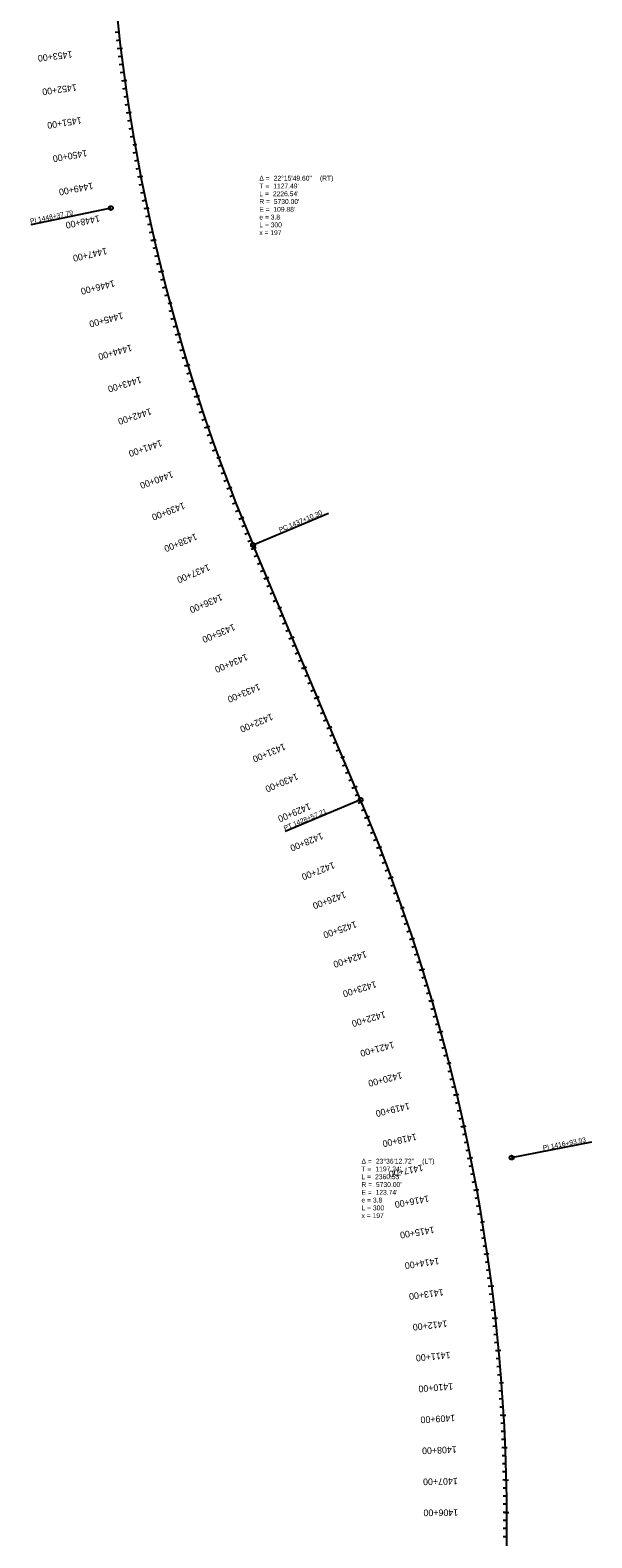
# Model space of a CAD drawing. Extents: x 20505176 to 20507119, y 7960287 to 7982631.
# Drawn here: x 20505239 to 20506971, y 7973323 to 7977971 of the extents above; entities that cross this region are included whole.
import ezdxf

# ---------------------------------------------------------------- set-up
doc = ezdxf.new("R2010")
doc.units = 0
for name, color, linetype in [('Alignment', 7, 'Continuous'), ('TextAlignment', 7, 'Continuous'), ('TextAlignmentLrg', 7, 'Continuous'), ('TextAlignmentSml', 7, 'Continuous')]:
    doc.layers.add(name, color=color, linetype=linetype)

msp = doc.modelspace()

# ---------------------------------------------------------------- linework, layer by layer
at = {"layer": 'Alignment'}
msp.add_line((20506257.8, 7975598.2), (20505926.1, 7976384.1), dxfattribs=at)
for centre, start, end in [((20511205.4, 7978611.7), 180.61343, 202.8772), ((20500978.6, 7973370.4), 359.27591, 22.87944)]:
    msp.add_arc(centre, 5730, start, end, dxfattribs=at)
at = {"layer": 'TextAlignment'}
for p, q in [((20505487.8, 7977422.9), (20505241.1, 7977371.6)), ((20505241.1, 7977371.6), (20505241.1, 7977371.6)), ((20505926.1, 7976384.1), (20506158.3, 7976482.1)), ((20506158.3, 7976482.1), (20506158.3, 7976482.1)), ((20506257.8, 7975598.2), (20506025.6, 7975500.2)), ((20506025.6, 7975500.2), (20506025.6, 7975500.2)), ((20506723.2, 7974495.1), (20506970.5, 7974543.5)), ((20506970.5, 7974543.5), (20506970.5, 7974543.5))]:
    msp.add_line(p, q, dxfattribs=at)
for centre in [(20505487.8, 7977422.9), (20505926.1, 7976384.1), (20506257.8, 7975598.2), (20506723.2, 7974495.1)]:
    msp.add_circle(centre, 6.24, dxfattribs=at)
at = {"layer": 'TextAlignmentLrg'}
for p, q in [((20505517.9, 7977915.3), (20505507, 7977913.9)), ((20505530.9, 7977816.1), (20505520.1, 7977814.6)), ((20505545.7, 7977717.2), (20505534.9, 7977715.5)), ((20505556.1, 7977617.5), (20505568.2, 7977619.6)), ((20505580.3, 7977520.2), (20505569.6, 7977518.2)), ((20505600.2, 7977422.2), (20505589.5, 7977420)), ((20505621.8, 7977324.6), (20505611.2, 7977322.2)), ((20505645.1, 7977227.4), (20505634.6, 7977224.7)), ((20505664.2, 7977129), (20505676.1, 7977132.1)), ((20505696.8, 7977034.2), (20505686.3, 7977031.2)), ((20505725.2, 7976938.3), (20505714.8, 7976935.1)), ((20505755.3, 7976842.9), (20505744.9, 7976839.5)), ((20505786.9, 7976748.1), (20505776.6, 7976744.5)), ((20505814.5, 7976651.7), (20505826, 7976655.9)), ((20505855.3, 7976560.1), (20505845.1, 7976556.2)), ((20505891.9, 7976467.1), (20505881.8, 7976463)), ((20505930.1, 7976374.7), (20505920.1, 7976370.4)), ((20505969, 7976282.5), (20505958.9, 7976278.3)), ((20506002.2, 7976188), (20506013.5, 7976192.8)), ((20506046.8, 7976098.2), (20506036.7, 7976094)), ((20506085.6, 7976006.1), (20506075.6, 7976001.9)), ((20506124.5, 7975914), (20506114.4, 7975909.7)), ((20506163.4, 7975821.8), (20506153.3, 7975817.6)), ((20506196.6, 7975727.3), (20506207.9, 7975732.1)), ((20506241.1, 7975637.6), (20506231.1, 7975633.3)), ((20506279.7, 7975545.3), (20506269.6, 7975541.2)), ((20506316.9, 7975452.5), (20506306.7, 7975448.5)), ((20506352.4, 7975359), (20506342.2, 7975355.2)), ((20506380.5, 7975262.9), (20506392.1, 7975267)), ((20506418.5, 7975170.3), (20506408.2, 7975166.8)), ((20506449.1, 7975075.1), (20506438.7, 7975071.8)), ((20506478, 7974979.3), (20506467.5, 7974976.3)), ((20506505.3, 7974883.1), (20506494.7, 7974880.2)), ((20506524.9, 7974784.9), (20506536.8, 7974788)), ((20506554.7, 7974689.3), (20506544.1, 7974686.8)), ((20506576.9, 7974591.8), (20506566.2, 7974589.5)), ((20506597.3, 7974493.9), (20506586.6, 7974491.8)), ((20506616.1, 7974395.7), (20506605.3, 7974393.8)), ((20506627.1, 7974296.2), (20506639.2, 7974298.2)), ((20506648.4, 7974198.4), (20506637.6, 7974196.8)), ((20506662, 7974099.3), (20506651.2, 7974097.9)), ((20506673.9, 7974000), (20506663, 7973998.8)), ((20506684, 7973900.5), (20506673.1, 7973899.5)), ((20506686.3, 7973800.4), (20506698.5, 7973801.3)), ((20506699, 7973701.1), (20506688.1, 7973700.5)), ((20506703.9, 7973601.2), (20506693, 7973600.8)), ((20506707.1, 7973501.3), (20506696.2, 7973501)), ((20506708.5, 7973401.3), (20506697.6, 7973401.2))]:
    msp.add_line(p, q, dxfattribs=at)
at = {"layer": 'TextAlignmentSml'}
for p, q in [((20505512, 7977964.9), (20505501.2, 7977963.7)), ((20505514.9, 7977940.1), (20505504.1, 7977938.8)), ((20505511.8, 7977914.5), (20505524, 7977916)), ((20505521, 7977890.4), (20505510.1, 7977889.1)), ((20505524.2, 7977865.7), (20505513.4, 7977864.2)), ((20505527.5, 7977840.9), (20505516.7, 7977839.4)), ((20505524.8, 7977815.3), (20505537, 7977817)), ((20505534.4, 7977791.4), (20505523.6, 7977789.8)), ((20505538.1, 7977766.6), (20505527.3, 7977765)), ((20505541.8, 7977741.9), (20505531, 7977740.2)), ((20505539.6, 7977716.2), (20505551.7, 7977718.2)), ((20505549.6, 7977692.5), (20505538.8, 7977690.8)), ((20505553.7, 7977667.9), (20505542.9, 7977666.1)), ((20505557.8, 7977643.2), (20505547.1, 7977641.4)), ((20505556.1, 7977617.5), (20505568.2, 7977619.6)), ((20505566.5, 7977594), (20505555.8, 7977592)), ((20505571, 7977569.4), (20505560.3, 7977567.4)), ((20505575.6, 7977544.8), (20505564.9, 7977542.8)), ((20505574.3, 7977519.1), (20505586.3, 7977521.4)), ((20505585.1, 7977495.7), (20505574.4, 7977493.6)), ((20505590.1, 7977471.2), (20505579.4, 7977469)), ((20505595.1, 7977446.7), (20505584.4, 7977444.5)), ((20505594.2, 7977421), (20505606.2, 7977423.5)), ((20505605.5, 7977397.8), (20505594.8, 7977395.5)), ((20505610.8, 7977373.4), (20505600.2, 7977371)), ((20505616.3, 7977349), (20505605.6, 7977346.6)), ((20505615.9, 7977323.2), (20505627.8, 7977326)), ((20505627.5, 7977300.3), (20505616.9, 7977297.8)), ((20505633.3, 7977275.9), (20505622.7, 7977273.4)), ((20505639.2, 7977251.6), (20505628.6, 7977249)), ((20505639.2, 7977225.9), (20505651.1, 7977228.8)), ((20505651.2, 7977203.1), (20505640.7, 7977200.4)), ((20505657.4, 7977178.9), (20505646.9, 7977176.2)), ((20505663.7, 7977154.7), (20505653.2, 7977151.9)), ((20505664.2, 7977129), (20505676.1, 7977132.1)), ((20505676.7, 7977106.4), (20505666.1, 7977103.5)), ((20505683.3, 7977082.3), (20505672.8, 7977079.4)), ((20505690, 7977058.2), (20505679.5, 7977055.3)), ((20505691, 7977032.5), (20505702.7, 7977035.9)), ((20505703.8, 7977010.2), (20505693.3, 7977007.1)), ((20505710.8, 7976986.2), (20505700.3, 7976983.1)), ((20505718, 7976962.2), (20505707.5, 7976959.1)), ((20505719.4, 7976936.5), (20505731.1, 7976940.1)), ((20505732.6, 7976914.4), (20505722.1, 7976911.2)), ((20505740, 7976890.5), (20505729.6, 7976887.2)), ((20505747.6, 7976866.7), (20505737.2, 7976863.4)), ((20505749.4, 7976841), (20505761.1, 7976844.8)), ((20505763, 7976819.1), (20505752.6, 7976815.7)), ((20505770.9, 7976795.4), (20505760.5, 7976791.9)), ((20505778.9, 7976771.7), (20505768.5, 7976768.2)), ((20505781.2, 7976746.1), (20505792.7, 7976750.1)), ((20505795.1, 7976724.4), (20505784.8, 7976720.8)), ((20505803.4, 7976700.8), (20505793.1, 7976697.2)), ((20505811.8, 7976677.3), (20505801.5, 7976673.6)), ((20505814.5, 7976651.7), (20505826, 7976655.9)), ((20505828.9, 7976630.3), (20505818.6, 7976626.5)), ((20505837.6, 7976606.9), (20505827.4, 7976603)), ((20505846.4, 7976583.5), (20505836.2, 7976579.6)), ((20505849.6, 7976557.9), (20505861, 7976562.3)), ((20505864.3, 7976536.8), (20505854.1, 7976532.8)), ((20505873.4, 7976513.5), (20505863.2, 7976509.5)), ((20505882.6, 7976490.3), (20505872.5, 7976486.2)), ((20505886.2, 7976464.8), (20505897.6, 7976469.3)), ((20505901.3, 7976443.9), (20505891.2, 7976439.8)), ((20505910.8, 7976420.8), (20505900.7, 7976416.6)), ((20505920.4, 7976397.7), (20505910.4, 7976393.5)), ((20505924.5, 7976372.3), (20505935.8, 7976377)), ((20505939.8, 7976351.6), (20505929.8, 7976347.4)), ((20505949.6, 7976328.6), (20505939.5, 7976324.3)), ((20505959.3, 7976305.5), (20505949.2, 7976301.3)), ((20505963.4, 7976280.1), (20505974.6, 7976284.9)), ((20505978.7, 7976259.5), (20505968.7, 7976255.2)), ((20505988.4, 7976236.4), (20505978.4, 7976232.2)), ((20505998.2, 7976213.4), (20505988.1, 7976209.2)), ((20506002.2, 7976188), (20506013.5, 7976192.8)), ((20506017.6, 7976167.3), (20506007.5, 7976163.1)), ((20506027.3, 7976144.3), (20506017.3, 7976140.1)), ((20506037, 7976121.3), (20506027, 7976117)), ((20506041.1, 7976095.9), (20506052.4, 7976100.6)), ((20506056.5, 7976075.2), (20506046.4, 7976071)), ((20506066.2, 7976052.2), (20506056.1, 7976047.9)), ((20506075.9, 7976029.1), (20506065.8, 7976024.9)), ((20506080, 7976003.7), (20506091.3, 7976008.5)), ((20506095.3, 7975983.1), (20506085.3, 7975978.8)), ((20506105.1, 7975960), (20506095, 7975955.8)), ((20506114.8, 7975937), (20506104.7, 7975932.8)), ((20506118.9, 7975911.6), (20506130.1, 7975916.4)), ((20506134.2, 7975890.9), (20506124.2, 7975886.7)), ((20506143.9, 7975867.9), (20506133.9, 7975863.7)), ((20506153.7, 7975844.9), (20506143.6, 7975840.6)), ((20506157.7, 7975819.5), (20506169, 7975824.2)), ((20506173.1, 7975798.8), (20506163, 7975794.6)), ((20506182.8, 7975775.8), (20506172.8, 7975771.5)), ((20506192.5, 7975752.7), (20506182.5, 7975748.5)), ((20506196.6, 7975727.3), (20506207.9, 7975732.1)), ((20506212, 7975706.7), (20506201.9, 7975702.4)), ((20506221.7, 7975683.6), (20506211.6, 7975679.4)), ((20506231.4, 7975660.6), (20506221.3, 7975656.4)), ((20506235.5, 7975635.2), (20506246.8, 7975640)), ((20506250.8, 7975614.5), (20506240.8, 7975610.3)), ((20506260.6, 7975591.5), (20506250.5, 7975587.3)), ((20506270.2, 7975568.4), (20506260.1, 7975564.2)), ((20506274.1, 7975543), (20506285.4, 7975547.7)), ((20506289.2, 7975522.2), (20506279.1, 7975518.1)), ((20506298.5, 7975499), (20506288.4, 7975494.9)), ((20506307.8, 7975475.8), (20506297.6, 7975471.7)), ((20506311.2, 7975450.3), (20506322.6, 7975454.7)), ((20506325.9, 7975429.2), (20506315.7, 7975425.3)), ((20506334.9, 7975405.8), (20506324.6, 7975401.9)), ((20506343.7, 7975382.4), (20506333.5, 7975378.6)), ((20506346.7, 7975356.9), (20506358.1, 7975361.1)), ((20506361, 7975335.5), (20506350.8, 7975331.8)), ((20506369.6, 7975312), (20506359.3, 7975308.3)), ((20506378, 7975288.5), (20506367.7, 7975284.8)), ((20506380.5, 7975262.9), (20506392.1, 7975267)), ((20506394.5, 7975241.3), (20506384.2, 7975237.8)), ((20506402.6, 7975217.7), (20506392.3, 7975214.1)), ((20506410.6, 7975194), (20506400.3, 7975190.5)), ((20506412.7, 7975168.3), (20506424.3, 7975172.2)), ((20506426.3, 7975146.5), (20506416, 7975143.1)), ((20506434, 7975122.7), (20506423.6, 7975119.4)), ((20506441.6, 7975098.9), (20506431.2, 7975095.6)), ((20506443.3, 7975073.2), (20506455, 7975076.9)), ((20506456.5, 7975051.2), (20506446.1, 7975048)), ((20506463.8, 7975027.3), (20506453.3, 7975024.1)), ((20506471, 7975003.3), (20506460.5, 7975000.2)), ((20506472.2, 7974977.6), (20506483.9, 7974981.1)), ((20506485, 7974955.3), (20506474.5, 7974952.3)), ((20506491.9, 7974931.3), (20506481.4, 7974928.3)), ((20506498.6, 7974907.2), (20506488.1, 7974904.3)), ((20506499.4, 7974881.5), (20506511.2, 7974884.7)), ((20506511.8, 7974859), (20506501.3, 7974856.2)), ((20506518.3, 7974834.8), (20506507.7, 7974832)), ((20506524.6, 7974810.7), (20506514, 7974807.9)), ((20506524.9, 7974784.9), (20506536.8, 7974788)), ((20506537, 7974762.2), (20506526.4, 7974759.5)), ((20506543, 7974737.9), (20506532.4, 7974735.3)), ((20506548.9, 7974713.6), (20506538.3, 7974711.1)), ((20506548.7, 7974687.9), (20506560.7, 7974690.7)), ((20506560.4, 7974665), (20506549.8, 7974662.5)), ((20506566, 7974640.6), (20506555.3, 7974638.2)), ((20506571.5, 7974616.2), (20506560.8, 7974613.9)), ((20506570.9, 7974590.5), (20506582.8, 7974593.1)), ((20506582.1, 7974567.4), (20506571.5, 7974565.1)), ((20506587.3, 7974542.9), (20506576.6, 7974540.7)), ((20506592.4, 7974518.4), (20506581.7, 7974516.3)), ((20506591.3, 7974492.7), (20506603.3, 7974495.1)), ((20506602.2, 7974469.4), (20506591.5, 7974467.3)), ((20506606.9, 7974444.9), (20506596.2, 7974442.8)), ((20506611.6, 7974420.3), (20506600.8, 7974418.3)), ((20506620.5, 7974371.1), (20506609.7, 7974369.2)), ((20506610.1, 7974394.6), (20506622.1, 7974396.8)), ((20506624.8, 7974346.5), (20506614, 7974344.6)), ((20506629, 7974321.8), (20506618.2, 7974320)), ((20506637.1, 7974272.5), (20506626.3, 7974270.8)), ((20506627.1, 7974296.2), (20506639.2, 7974298.2)), ((20506641, 7974247.8), (20506630.2, 7974246.1)), ((20506644.8, 7974223.1), (20506634, 7974221.5)), ((20506642.4, 7974197.5), (20506654.5, 7974199.2)), ((20506652, 7974173.6), (20506641.2, 7974172.1)), ((20506655.4, 7974148.9), (20506644.6, 7974147.4)), ((20506658.8, 7974124.1), (20506648, 7974122.6)), ((20506655.9, 7974098.5), (20506668.1, 7974100.1)), ((20506665.1, 7974074.5), (20506654.3, 7974073.1)), ((20506668.2, 7974049.7), (20506657.3, 7974048.4)), ((20506671.1, 7974024.8), (20506660.2, 7974023.6)), ((20506667.8, 7973999.3), (20506679.9, 7974000.7)), ((20506676.6, 7973975.1), (20506665.7, 7973974)), ((20506679.1, 7973950.3), (20506668.3, 7973949.2)), ((20506681.6, 7973925.4), (20506670.8, 7973924.3)), ((20506677.9, 7973899.9), (20506690.1, 7973901.1)), ((20506686.2, 7973875.6), (20506675.4, 7973874.6)), ((20506688.4, 7973850.7), (20506677.5, 7973849.8)), ((20506690.4, 7973825.8), (20506679.6, 7973824.9)), ((20506694.2, 7973775.9), (20506683.3, 7973775.2)), ((20506686.3, 7973800.4), (20506698.5, 7973801.3)), ((20506695.9, 7973751), (20506685, 7973750.3)), ((20506697.5, 7973726), (20506686.6, 7973725.4)), ((20506700.4, 7973676.1), (20506689.5, 7973675.5)), ((20506692.9, 7973700.7), (20506705.1, 7973701.4)), ((20506701.7, 7973651.2), (20506690.8, 7973650.6)), ((20506702.9, 7973626.2), (20506691.9, 7973625.7)), ((20506704.9, 7973576.2), (20506694, 7973575.8)), ((20506697.8, 7973601), (20506710, 7973601.4)), ((20506705.7, 7973551.2), (20506694.8, 7973550.9)), ((20506706.4, 7973526.2), (20506695.5, 7973525.9)), ((20506701, 7973501.1), (20506713.2, 7973501.4)), ((20506707.6, 7973476.3), (20506696.7, 7973476.1)), ((20506708, 7973451.3), (20506697.1, 7973451.1)), ((20506708.3, 7973426.3), (20506697.4, 7973426.2)), ((20506702.4, 7973401.2), (20506714.6, 7973401.3)), ((20506708.6, 7973376.3), (20506697.6, 7973376.3)), ((20506708.5, 7973351.3), (20506697.6, 7973351.3)), ((20506708.4, 7973326.3), (20506697.5, 7973326.3))]:
    msp.add_line(p, q, dxfattribs=at)

# ---------------------------------------------------------------- texts
at = {"layer": 'TextAlignment'}
for s, p in [(' (RT)', (20506126.5, 7977507.5)), ('T = ', (20505945.4, 7977483.5)), ('Δ = ', (20505945.4, 7977507.5)), ("1127.49'", (20505988.3, 7977483.5)), ('22°15\'49.60"', (20505989.8, 7977507.5)), ('L = ', (20505945.4, 7977459.5)), ('R = ', (20505945.4, 7977435.5)), ("2226.54'", (20505987.2, 7977459.5)), ("5730.00'", (20505990, 7977435.5)), ('e = 3.8', (20505945.4, 7977387.5)), ('E = ', (20505945.4, 7977411.5)), ("109.88'", (20505988.7, 7977411.5)), ('x = 197', (20505945.4, 7977339.5)), ('L = 300', (20505945.4, 7977363.5)), ('T = ', (20506260.5, 7974452.7)), ('Δ = ', (20506260.5, 7974476.7)), ("1197.24'", (20506303.4, 7974452.7)), ('23°36\'12.72"', (20506304.9, 7974476.7)), (' (LT)', (20506441.6, 7974476.7)), ('L = ', (20506260.5, 7974428.7)), ('R = ', (20506260.5, 7974404.7)), ("2360.53'", (20506302.3, 7974428.7)), ("5730.00'", (20506305.1, 7974404.7)), ('e = 3.8', (20506260.5, 7974356.7)), ('E = ', (20506260.5, 7974380.7)), ("123.74'", (20506303.8, 7974380.7)), ('x = 197', (20506260.5, 7974308.7)), ('L = 300', (20506260.5, 7974332.7))]:
    msp.add_text(s, height=15, dxfattribs=at).set_placement(p)
for s, rotation, p in [('PI ', 11.7453, (20505240.4, 7977374.9)), ('1448+37.79', 11.7453, (20505264.9, 7977380)), ('1437+10.30', 22.8772, (20506039.9, 7976435.7)), ('PC', 22.8772, (20506009.2, 7976422.8)), ('PT', 22.8794, (20506024.3, 7975503.2)), ('1428+57.21', 22.8794, (20506053.3, 7975515.5)), ('1416+93.93', 11.0777, (20506845.4, 7974522.4)), ('PI ', 11.0777, (20506820.8, 7974517.6))]:
    msp.add_text(s, height=15, rotation=rotation, dxfattribs=at).set_placement(p)
at = {"layer": 'TextAlignmentLrg'}
for s, rotation, p in [('1450+00', 189.9811, (20505412.6, 7977602.6)), ('1445+00', 194.9808, (20505522.6, 7977101.6)), ('1440+00', 199.9804, (20505675.8, 7976612.1)), ('1435+00', 202.8763, (20505865.7, 7976141.5)), ('1430+00', 202.8763, (20506060.1, 7975680.8)), ('1425+00', 199.3076, (20506241.4, 7975225)), ('1420+00', 194.3079, (20506383, 7974759.3)), ('1415+00', 189.3083, (20506483.4, 7974283)), ('1410+00', 184.3087, (20506542, 7973799.8))]:
    msp.add_text(s, height=20.4, rotation=rotation, dxfattribs=at).set_placement(p)
at = {"layer": 'TextAlignmentSml'}
for s, rotation, p in [('1453+00', 186.9814, (20505367.8, 7977907.2)), ('1452+00', 187.9813, (20505380.9, 7977805.4)), ('1451+00', 188.9812, (20505395.9, 7977703.9)), ('1450+00', 189.9811, (20505412.6, 7977602.6)), ('1449+00', 190.9811, (20505431.1, 7977501.7)), ('1448+00', 191.981, (20505451.4, 7977401.1)), ('1447+00', 192.9809, (20505473.4, 7977300.9)), ('1446+00', 193.9808, (20505497.1, 7977201)), ('1445+00', 194.9808, (20505522.6, 7977101.6)), ('1444+00', 195.9807, (20505549.8, 7977002.7)), ('1443+00', 196.9806, (20505578.8, 7976904.2)), ('1442+00', 197.9806, (20505609.4, 7976806.3)), ('1441+00', 198.9805, (20505641.8, 7976708.9)), ('1440+00', 199.9804, (20505675.8, 7976612.1)), ('1439+00', 200.9803, (20505711.6, 7976515.9)), ('1438+00', 201.9803, (20505749, 7976420.4)), ('1437+00', 202.8763, (20505788, 7976325.7)), ('1436+00', 202.8763, (20505826.8, 7976233.6)), ('1435+00', 202.8763, (20505865.7, 7976141.5)), ('1434+00', 202.8763, (20505904.6, 7976049.3)), ('1433+00', 202.8763, (20505943.5, 7975957.2)), ('1432+00', 202.8763, (20505982.3, 7975865.1)), ('1431+00', 202.8763, (20506021.2, 7975772.9)), ('1430+00', 202.8763, (20506060.1, 7975680.8)), ('1429+00', 202.8763, (20506099, 7975588.7)), ('1428+00', 202.3073, (20506137.1, 7975497.8)), ('1427+00', 201.3074, (20506173.4, 7975407.5)), ('1426+00', 200.3075, (20506208.2, 7975316.5)), ('1425+00', 199.3076, (20506241.4, 7975225)), ('1424+00', 198.3076, (20506272.9, 7975132.8)), ('1423+00', 197.3077, (20506302.9, 7975040.2)), ('1422+00', 196.3078, (20506331.2, 7974947)), ('1421+00', 195.3078, (20506357.9, 7974853.4)), ('1420+00', 194.3079, (20506383, 7974759.3)), ('1419+00', 193.308, (20506406.4, 7974664.7)), ('1418+00', 192.3081, (20506428.1, 7974569.8)), ('1417+00', 191.3081, (20506448.2, 7974474.5)), ('1416+00', 190.3082, (20506466.7, 7974378.9)), ('1415+00', 189.3083, (20506483.4, 7974283)), ('1414+00', 188.3084, (20506498.5, 7974186.8)), ('1413+00', 187.3084, (20506511.9, 7974090.3)), ('1412+00', 186.3085, (20506523.7, 7973993.6)), ('1411+00', 185.3086, (20506533.7, 7973896.8)), ('1410+00', 184.3087, (20506542, 7973799.8)), ('1409+00', 183.3087, (20506548.7, 7973702.6)), ('1408+00', 182.3088, (20506553.6, 7973605.4)), ('1407+00', 181.3089, (20506556.9, 7973508)), ('1406+00', 180.309, (20506558.4, 7973410.7))]:
    msp.add_text(s, height=20.4, rotation=rotation, dxfattribs=at).set_placement(p)

doc.saveas('drawing.dxf')
